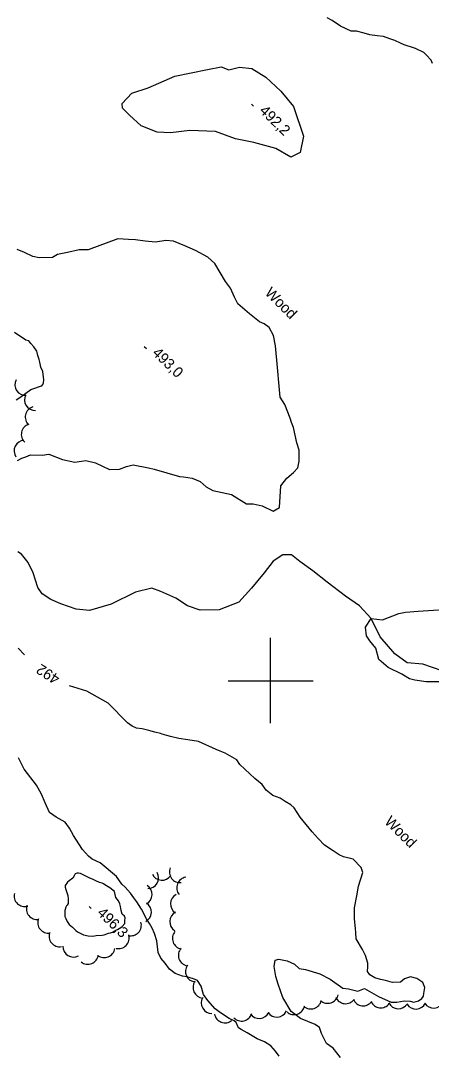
# Model space of a CAD drawing. Extents: x 642515 to 647219, y 6080136 to 6084356.
# Drawn here: x 644129.6 to 644245.5, y 6080895.6 to 6081186.1 of the extents above; entities that cross this region are included whole.
import ezdxf

# ---------------------------------------------------------------- set-up
doc = ezdxf.new("R2010")
doc.units = 0
for name, color, linetype in [('Level 1', 7, 'Continuous'), ('Level 2', 7, 'Continuous'), ('Level 3', 7, 'Continuous'), ('Level 4', 7, 'Continuous'), ('Level 44', 7, 'Continuous'), ('Level 61', 7, 'Continuous')]:
    doc.layers.add(name, color=color, linetype=linetype)

msp = doc.modelspace()

# ---------------------------------------------------------------- linework, layer by layer
at = {"layer": 'Level 1'}
for points in [[(644245.84, 6081174.06), (644245.46, 6081175), (644244.06, 6081176.52), (644243.38, 6081177.12), (644241.04, 6081178.26), (644240.46, 6081178.46), (644237.82, 6081179.26), (644236.74, 6081179.75), (644235.15, 6081180.53), (644233.74, 6081181.01), (644232.01, 6081181.62), (644230.21, 6081181.82), (644228.09, 6081182.16), (644226.52, 6081182.63), (644224.39, 6081183.13), (644222.86, 6081183.11), (644219.85, 6081184.52), (644217.52, 6081186.11), (644216.14, 6081186.94)], [(644248.1, 6080999.77), (644244.06, 6080999.82), (644240.8, 6081000.25), (644239.32, 6081000.64), (644237.13, 6081001.95), (644233.29, 6081003.79), (644230.72, 6081006.04), (644229.86, 6081009.22), (644228.1, 6081011.36), (644227.2, 6081012.76), (644226.88, 6081015.16), (644228.49, 6081017.66), (644231.75, 6081017.23), (644236.32, 6081018.99), (644238.23, 6081019.44), (644241.77, 6081019.67), (644253.35, 6081020.45)]]:
    msp.add_lwpolyline(points, dxfattribs=at)
at = {"layer": 'Level 2'}
for points in [[(644188.37, 6081172.29), (644191.39, 6081172.98), (644194.88, 6081172.65), (644198.76, 6081170.16), (644203.05, 6081166.25), (644206.65, 6081161.89), (644209.46, 6081153.53), (644208.47, 6081148.95), (644205.82, 6081147.64), (644201.62, 6081150.1), (644195.38, 6081151.78), (644190.22, 6081152.81), (644184.6, 6081154.85), (644177.32, 6081155.17), (644171.88, 6081154.49), (644168.15, 6081154.72), (644163.6, 6081156.44), (644160.33, 6081159.45), (644158.34, 6081161.49), (644158.26, 6081162.78), (644160.97, 6081165.7), (644165.63, 6081167.22), (644173.16, 6081170.47), (644182.39, 6081172.38), (644186.21, 6081173.12), (644188.37, 6081172.29)], [(644167.33, 6081059.68), (644174.48, 6081057.66), (644175.62, 6081057.57), (644177.98, 6081057.16), (644180.31, 6081056.19), (644181.93, 6081054.76), (644183.86, 6081053.68), (644189.1, 6081052.58), (644193.31, 6081049.96), (644195.24, 6081049.93), (644197.78, 6081049.37), (644200.87, 6081047.88), (644202.66, 6081048.89), (644203.05, 6081055.05), (644204.77, 6081057.18), (644206.6, 6081058.75), (644207.8, 6081060.12), (644208.24, 6081062.01), (644208.2, 6081065.07), (644207.58, 6081067.13), (644206.56, 6081071.5), (644206.07, 6081072.83), (644205.66, 6081074.1), (644204.2, 6081077.95), (644202.85, 6081080.04), (644202.78, 6081081.01), (644201.92, 6081090.39), (644201.71, 6081092.39), (644201.57, 6081094.48), (644200.97, 6081097.42), (644199.77, 6081099.68), (644198.34, 6081100.64), (644197.01, 6081101.19), (644194.19, 6081103.51), (644190.86, 6081106.27), (644190.01, 6081108.23), (644188.87, 6081110.74), (644187.46, 6081112.58), (644184.38, 6081117.7), (644182.41, 6081119.42), (644178.97, 6081121.37), (644175.98, 6081122.62), (644172.75, 6081123.94), (644170.64, 6081124.12), (644167.68, 6081123.68), (644164.76, 6081123.97), (644162.07, 6081124.36), (644160.05, 6081124.46), (644157.05, 6081124.67), (644148.7, 6081121.53), (644146.12, 6081121.52), (644142.87, 6081120.73)], [(644142.87, 6081120.73), (644140, 6081120.22), (644138.6, 6081119.32), (644134.9, 6081119.23), (644133.1, 6081119.6), (644130.76, 6081120.73), (644128.69, 6081121.64)], [(644128.35, 6081079.25), (644129.7, 6081080.1), (644132.51, 6081082.18), (644133.37, 6081082.48), (644135.26, 6081083.09), (644135.58, 6081083.19), (644135.88, 6081083.54), (644136.05, 6081084.07), (644136.19, 6081084.93), (644135.88, 6081087.24), (644135.35, 6081088.46), (644135.06, 6081089.85), (644134.84, 6081090.64), (644134.45, 6081091.74), (644134.31, 6081092.61), (644134.2, 6081093.01), (644133.32, 6081094.16), (644132.53, 6081095.15), (644132, 6081095.84), (644131.1, 6081096.11), (644127.93, 6081098.27)], [(644128.76, 6081062.11), (644130.01, 6081062.83), (644131.11, 6081063.23), (644132.45, 6081063.72), (644135.76, 6081063.7), (644137.6, 6081063.91), (644141.41, 6081062.39), (644144.92, 6081061.73), (644146.77, 6081061.94), (644148.04, 6081062.18), (644150.75, 6081061.48), (644154.74, 6081059.65), (644157.49, 6081059.67), (644159.53, 6081060.45), (644161.35, 6081060.97), (644165.69, 6081060.05), (644167.33, 6081059.68)], [(644130.71, 6081007.43), (644128.93, 6081009.29)], [(644209.96, 6080918.71), (644214.07, 6080917.53), (644216.92, 6080915.95), (644220.48, 6080913.44), (644222.1, 6080913.23), (644223.99, 6080912.79), (644224.73, 6080912.59), (644226.61, 6080913.37), (644230.55, 6080911.13), (644234.13, 6080909.51), (644235.75, 6080909.46), (644237.81, 6080909.92), (644239.52, 6080909.79), (644240.5, 6080909.53), (644241.85, 6080909.86), (644242.77, 6080910.57), (644243.3, 6080911.17), (644243.4, 6080911.98), (644243.62, 6080913.61), (644243.04, 6080915.03), (644241.35, 6080916.2), (644239.63, 6080916.65), (644237.89, 6080916.05), (644236.82, 6080915.18), (644234.57, 6080915.03), (644232.51, 6080915.61), (644231.12, 6080915.92), (644229.56, 6080916.38), (644228.14, 6080917.18), (644227.5, 6080918.18), (644227.58, 6080919.48), (644227.59, 6080920.53), (644226.88, 6080922.66), (644226.05, 6080924.3), (644224.32, 6080927.33), (644224.2, 6080929.09), (644224.12, 6080930.22), (644223.78, 6080932.94), (644223.84, 6080934.56), (644223.82, 6080936.09), (644224.48, 6080939.44), (644224.94, 6080942.21), (644226.14, 6080946), (644225.73, 6080947.43), (644223.39, 6080949.77), (644220.68, 6080950.48), (644219.52, 6080951.05), (644217.75, 6080952.14), (644215.38, 6080953.76), (644213.56, 6080955.65), (644211.83, 6080957.47), (644208.49, 6080961.6), (644206.78, 6080964.31), (644205.84, 6080965.14), (644204.24, 6080966.08), (644202.81, 6080967.03), (644200.74, 6080967.78), (644198.87, 6080969.27), (644197.8, 6080970.81), (644195.66, 6080972.53), (644191.45, 6080976.52), (644190.63, 6080977.84), (644187.37, 6080979.64), (644185.95, 6080980.27), (644184.8, 6080980.67), (644179.81, 6080982.92), (644176.79, 6080983.45), (644174.26, 6080983.84), (644171.88, 6080984.41), (644170.9, 6080984.67), (644169.58, 6080985.06), (644169.09, 6080985.19), (644167.45, 6080985.57), (644165.8, 6080986.1), (644163.92, 6080986.54), (644162.29, 6080986.75), (644161.12, 6080987.32), (644159.77, 6080988.2), (644154.32, 6080993.73), (644148.29, 6080997.19), (644143.38, 6080998.65)], [(644159.09, 6080941.92), (644158.15, 6080942.75), (644156.71, 6080944.9), (644152.11, 6080948.78), (644149.86, 6080949.84), (644148.76, 6080950.66), (644147.11, 6080952.56), (644146.04, 6080954.1), (644144.51, 6080956.49), (644143.41, 6080958.51), (644142.17, 6080960.2), (644139.66, 6080961.65), (644137.8, 6080962.97), (644136.57, 6080965.71), (644135.52, 6080968.13), (644134.14, 6080970.7), (644130.63, 6080975.14), (644129.05, 6080978.33)], [(644202.52, 6080894.24), (644201.54, 6080895.71), (644200.23, 6080897.15), (644198.38, 6080898.32), (644196.4, 6080899.15), (644193.54, 6080900.89), (644191.87, 6080901.75), (644191.12, 6080902.26), (644190.45, 6080903.75), (644189.85, 6080904.27), (644188.44, 6080904.9), (644187.18, 6080905.7), (644185.66, 6080906.73), (644184.48, 6080907.62), (644182.47, 6080909.98), (644181.23, 6080911.67), (644180.59, 6080914.04), (644179.52, 6080915.58), (644178.44, 6080916.07), (644176.55, 6080916.67), (644175.33, 6080916.83), (644173.27, 6080917.58), (644171.65, 6080918.84), (644170.41, 6080920.53), (644169.19, 6080921.9), (644168.45, 6080923.46), (644168.06, 6080926.82), (644167.44, 6080928.87), (644166.78, 6080930.36), (644165.97, 6080931.67), (644165.16, 6080932.98), (644163.77, 6080935.71), (644162.42, 6080937.8), (644161.55, 6080938.86), (644160.65, 6080940.25), (644159.09, 6080941.92)], [(644219.84, 6080893.88), (644217.8, 6080896.56), (644215.94, 6080897.89), (644214.46, 6080900.7), (644213.95, 6080902.36), (644212.69, 6080903.16), (644208.62, 6080904.9), (644205.99, 6080906.91), (644203.63, 6080910.78), (644202.25, 6080914.56), (644201.62, 6080916.78), (644201.19, 6080919.57), (644201.4, 6080921.36), (644202.51, 6080921.6), (644204.8, 6080921.11), (644206.88, 6080920.2), (644208.25, 6080919), (644209.96, 6080918.71)]]:
    msp.add_lwpolyline(points, dxfattribs=at)
msp.add_lwpolyline([(644156.51, 6080938.98), (644156.16, 6080940.73), (644154.82, 6080941.69), (644153.4, 6080942.57), (644153.02, 6080942.83), (644152.65, 6080943.01), (644151.87, 6080943.24), (644150.88, 6080943.66), (644149.92, 6080944.21), (644149.19, 6080944.41), (644148.61, 6080944.69), (644147.86, 6080945.13), (644147.32, 6080945.38), (644146.5, 6080945.73), (644146.01, 6080945.86), (644145.56, 6080945.88), (644145.06, 6080945.65), (644144.73, 6080945.1), (644144.32, 6080944.48), (644143.36, 6080943.74), (644142.83, 6080943.3), (644142.19, 6080942.42), (644142.19, 6080941.9), (644142.35, 6080941.22), (644142.93, 6080939.57), (644143.06, 6080938.61), (644143.07, 6080937.93), (644143.02, 6080937.29), (644142.81, 6080936.87), (644142.62, 6080936.66), (644142.36, 6080936.28), (644142.09, 6080935.38), (644142.15, 6080933.66), (644142.35, 6080933.11), (644142.76, 6080932.21), (644143.29, 6080931.43), (644144.23, 6080930.61), (644145.2, 6080929.74), (644145.71, 6080929.29), (644147.33, 6080928.46), (644148.71, 6080928.22), (644150, 6080928.14), (644150.91, 6080928.32), (644152.64, 6080928.38), (644153.19, 6080928.49), (644154.41, 6080928.93), (644154.97, 6080929.04), (644155.6, 6080929.24), (644156.45, 6080929.77), (644156.96, 6080930.01), (644157.86, 6080930.5), (644158.28, 6080930.81), (644159.03, 6080931.66), (644159.02, 6080932.5), (644159.14, 6080933.31), (644158.95, 6080933.78), (644158.27, 6080934.3), (644158.01, 6080935.29), (644157.82, 6080936.45), (644157.61, 6080937.24), (644157.25, 6080938.02)], close=True, dxfattribs=at)
at = {"layer": 'Level 3'}
for p, q in [((644194.73, 6081162.54), (644195.3, 6081161.98)), ((644164.53, 6081094.28), (644165.1, 6081093.72)), ((644148.98, 6080936.48), (644149.55, 6080935.92))]:
    msp.add_line(p, q, dxfattribs=at)
at = {"layer": 'Level 4'}
msp.add_lwpolyline([(644248.55, 6081002.87), (644243.09, 6081004.76), (644238.7, 6081005.1), (644235.21, 6081007.69), (644231.09, 6081012.5), (644228.49, 6081017.66), (644225.26, 6081021.23), (644221.28, 6081023.95), (644216.09, 6081027.88), (644212.08, 6081031.08), (644208.35, 6081033.73), (644206.05, 6081035.59), (644203.62, 6081035.59), (644200.84, 6081033.78), (644198.31, 6081030.54), (644194.8, 6081026.18), (644191.19, 6081022.22), (644185.68, 6081020.07), (644180.27, 6081019.95), (644176.72, 6081021.24), (644173.42, 6081023.35), (644169.18, 6081025.25), (644166.69, 6081026.21), (644162.01, 6081025), (644155.21, 6081021.71), (644149.11, 6081019.92), (644145.3, 6081020.23), (644140.97, 6081021.74), (644138.18, 6081022.97), (644135.69, 6081024.61), (644134.45, 6081026.38), (644133.2, 6081030.49), (644131.76, 6081033.42), (644129.9, 6081035.8), (644128.86, 6081036.41)], dxfattribs=at)
at = {"layer": 'Level 44'}
for centre, start, end in [((644131.03, 6081083.47), 152.6685, 272.6464), ((644133.72, 6081079.26), 152.6685, 272.6464), ((644133.93, 6081074.38), 107.3209, 227.2988), ((644132.83, 6081069.5), 107.3209, 227.2988), ((644130.8, 6081064.88), 94.4446, 214.4225), ((644165.56, 6080944.53), 269.4421, 29.4201), ((644174.58, 6080946.18), 156.6254, 276.6033), ((644169.49, 6080946.87), 205.9123, 325.8903), ((644176.67, 6080941.75), 98.9908, 218.9687), ((644130.79, 6080939.44), 166.7227, 286.7006), ((644163.72, 6080939.86), 297.6322, 57.6101), ((644163.52, 6080934.87), 297.6322, 57.6101), ((644174.91, 6080937.17), 117.6322, 237.6101), ((644134.25, 6080935.8), 159.7679, 279.7458), ((644174.7, 6080932.18), 117.6322, 237.6101), ((644137.45, 6080931.96), 159.7679, 279.7458), ((644160.7, 6080931.21), 256.4975, 16.4755), ((644140.65, 6080928.11), 159.7679, 279.7458), ((644157.25, 6080927.58), 256.4975, 16.4755), ((644175.46, 6080927.44), 139.6229, 259.6009), ((644144.53, 6080925.22), 178.6739, 298.6518), ((644148.58, 6080923.19), 231.9226, 351.9005), ((644153.22, 6080925.05), 231.9226, 351.9005), ((644177.13, 6080922.73), 139.6229, 259.6009), ((644179.13, 6080918.19), 145.0615, 265.0394), ((644181.25, 6080913.66), 145.0615, 265.0394), ((644216.24, 6080912.17), 228.5148, 348.4927), ((644221.29, 6080912.07), 203.2901, 323.268), ((644183.6, 6080909.28), 149.8873, 269.8653), ((644206.76, 6080909), 228.5148, 348.4927), ((644211.5, 6080910.59), 228.5148, 348.4927), ((644226.25, 6080911.48), 203.2901, 323.268), ((644231.22, 6080910.9), 203.2901, 323.268), ((644236.19, 6080910.66), 207.4157, 327.3937), ((644241.15, 6080910.56), 213.2469, 333.2249), ((644246.15, 6080910.84), 213.2469, 333.2249), ((644187.28, 6080906.67), 189.7896, 309.7676), ((644191.95, 6080907.16), 222.5893, 342.5673), ((644196.92, 6080907.9), 214.6541, 334.632), ((644201.91, 6080908.3), 214.6541, 334.632)]:
    msp.add_arc(centre, 3, start, end, dxfattribs=at)
at = {"layer": 'Level 61'}
for p, q in [((644200, 6081012.16), (644200, 6080988.16)), ((644212.16, 6081000), (644188.16, 6081000))]:
    msp.add_line(p, q, dxfattribs=at)

# ---------------------------------------------------------------- texts
at = {"layer": 'Level 2'}
msp.add_text('492', height=3, rotation=147.0275, dxfattribs=at).set_placement((644140.97, 6081001.34))
at = {"layer": 'Level 3'}
for s, p in [('492,2', (644196.76, 6081160.5)), ('493,0', (644166.56, 6081092.24)), ('496,3', (644151.01, 6080934.43))]:
    msp.add_text(s, height=3, rotation=315.59, dxfattribs=at).set_placement(p)
at = {"layer": 'Level 44'}
for p in [(644198.34, 6081109.17), (644232.08, 6080960.13)]:
    msp.add_text('Wood', height=3, rotation=315.1749, dxfattribs=at).set_placement(p)

doc.saveas('drawing.dxf')
